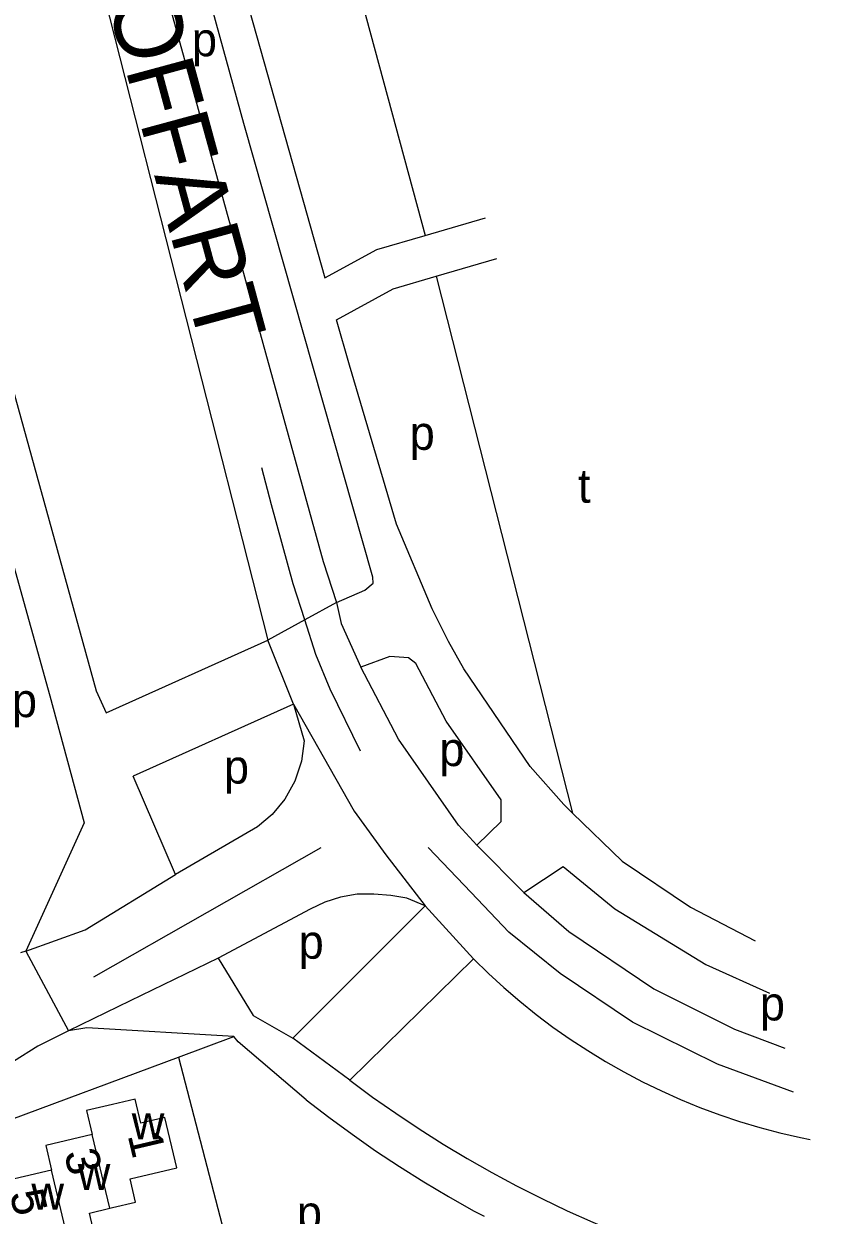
# Model space of a CAD drawing. Extents: x 157646 to 159241, y 379213 to 381217.
# Drawn here: x 159089.5 to 159185.7, y 380734 to 380874.9 of the extents above; entities that cross this region are included whole.
import ezdxf

# ---------------------------------------------------------------- set-up
doc = ezdxf.new("R2010")
doc.units = 0
for name, color, linetype in [('BLT_Basislijn', 7, 'Continuous'), ('BLT_Bebouwing', 7, 'Continuous'), ('BLT_Centroide', 7, 'Continuous'), ('BLT_Huisnummer', 7, 'Continuous'), ('BLT_Huisnummer_ tussenligend', 7, 'Continuous'), ('BLT_Onderverdeling_panden', 7, 'Continuous'), ('BLT_Straatnaam_hoofdweg', 7, 'Continuous'), ('BLT_Vlakafsluiter', 7, 'Continuous')]:
    doc.layers.add(name, color=color, linetype=linetype)

msp = doc.modelspace()

# ---------------------------------------------------------------- linework, layer by layer
at = {"layer": 'BLT_Basislijn'}
for p, q in [((159097.22, 380885.26), (159118.39, 380801.95)), ((159137, 380849.84), (159144.12, 380851.92)), ((159138.27, 380845), (159145.45, 380847.1)), ((159138.27, 380845), (159154.43, 380781.49)), ((159121.41, 380794.39), (159118.39, 380801.95)), ((159121.41, 380794.39), (159102.45, 380785.88)), ((159107.45, 380774.23), (159102.45, 380785.88)), ((159153.37, 380782.52), (159154.43, 380781.49)), ((159096.65, 380780.35), (159089.77, 380765.17)), ((159117.14, 380779.87), (159107.45, 380774.23)), ((159097.8, 380762.14), (159124.67, 380777.46)), ((159148.65, 380772.12), (159143.08, 380777.73)), ((159123.38, 380770.15), (159112.51, 380764.37)), ((159136.99, 380770.53), (159121.34, 380754.91)), ((159136.99, 380770.53), (159142.7, 380764.29)), ((159089.77, 380765.17), (159089.11, 380764.99)), ((159112.51, 380764.37), (159116.63, 380757.59)), ((159142.7, 380764.29), (159128.09, 380749.91)), ((159116.63, 380757.59), (159121.34, 380754.91)), ((159107.8, 380752.64), (159114.36, 380755.08)), ((159128.09, 380749.91), (159121.34, 380754.91)), ((159035.86, 380725.94), (159107.8, 380752.64)), ((159107.8, 380752.64), (159115.84, 380721.89))]:
    msp.add_line(p, q, dxfattribs=at)
for points in [[(159061.42, 381122.18), (159087.3, 381027.91), (159116.68, 380924.86), (159137, 380849.84)], [(159051.94, 381105.75), (159100, 380933.91), (159125.11, 380844.8)], [(159126.48, 380806.41), (159129.85, 380807.86), (159130.83, 380808.7), (159130.78, 380809.42), (159115.53, 380863.06), (159100, 380919.55), (159083.47, 380977.99), (159078.6, 380977.14)], [(159078.6, 380977.14), (159100, 380901.47), (159124.92, 380811.25), (159126.48, 380806.41)], [(159071.61, 380891.71), (159098.09, 380795.96), (159099.25, 380793.36), (159118.39, 380801.95)], [(159125.11, 380844.8), (159131.28, 380848.16), (159137, 380849.84)], [(159126.5, 380839.86), (159133.2, 380843.51), (159138.27, 380845)], [(159153.37, 380782.52), (159149.41, 380787.04), (159141.55, 380798.57), (159139.74, 380801.79), (159137.8, 380805.67), (159133.6, 380815.67), (159128.02, 380834.49), (159126.5, 380839.86)], [(159122.75, 380804.35), (159121.39, 380808.61), (159118.83, 380817.98), (159117.65, 380822.33)], [(159085.81, 380819.61), (159092.6, 380795.38), (159096.65, 380780.35)], [(159126.48, 380806.41), (159127.07, 380803.93), (159129.36, 380798.75)], [(159129.34, 380788.85), (159125.73, 380796.18), (159124.04, 380800.28), (159122.75, 380804.35)], [(159143.08, 380777.73), (159145.97, 380780.53), (159145.99, 380783.08), (159139.48, 380792.38), (159135.89, 380799.21), (159135.03, 380799.89), (159132.8, 380800.02), (159129.36, 380798.75)], [(159143.08, 380777.73), (159140.94, 380780.09), (159133.82, 380790.24), (159129.36, 380798.75)], [(159121.41, 380794.39), (159122.66, 380790.06), (159122.35, 380787.64), (159121.59, 380785.29), (159120.4, 380783.16), (159118.89, 380781.33), (159117.14, 380779.87)], [(159154.43, 380781.49), (159160.28, 380775.81), (159168.37, 380770.37), (159176.02, 380766.39)], [(159180.54, 380748.52), (159171.57, 380751.81), (159161.51, 380756.8), (159152.95, 380762.52), (159146.9, 380767.43), (159142.41, 380772.13), (159137.34, 380777.44)], [(159148.65, 380772.12), (159153.32, 380775.2), (159159.43, 380770.18), (159170.18, 380763.59), (159177.73, 380760.22)], [(159089.77, 380765.17), (159096.79, 380767.72), (159107.45, 380774.23)], [(159148.65, 380772.12), (159153.99, 380767.52), (159164.04, 380760.73), (159173.59, 380755.96), (159179.53, 380753.71)], [(159136.99, 380770.53), (159134.8, 380771.43), (159132.92, 380771.77), (159130.93, 380771.94), (159128.93, 380771.91), (159126.96, 380771.58), (159125.1, 380770.99), (159123.38, 380770.15)], [(159112.51, 380764.37), (159102.08, 380759.31), (159094.81, 380755.74)], [(159142.7, 380764.29), (159144.47, 380762.55), (159146.3, 380760.88), (159148.18, 380759.26), (159150.12, 380757.7), (159152.1, 380756.21), (159154.14, 380754.78), (159156.21, 380753.42), (159158.33, 380752.12), (159160.49, 380750.9), (159162.69, 380749.74), (159164.92, 380748.66), (159167.19, 380747.64), (159169.49, 380746.71), (159171.82, 380745.84), (159174.17, 380745.05), (159176.55, 380744.34), (159178.95, 380743.71), (159181.37, 380743.15), (159182.51, 380742.92)], [(159094.81, 380755.74), (159091.19, 380753.93), (159088.28, 380752.14), (159087.76, 380751.2)], [(159114.36, 380755.08), (159096.98, 380756.11), (159094.81, 380755.74)], [(159122.91, 380747.6), (159114.87, 380754.47), (159114.36, 380755.08)], [(159128.09, 380749.91), (159130.77, 380747.93), (159133.5, 380746.01), (159136.28, 380744.16), (159139.1, 380742.37), (159141.96, 380740.65), (159144.86, 380739), (159147.79, 380737.43), (159150.77, 380735.92), (159153.78, 380734.48), (159156.83, 380733.12), (159159.9, 380731.83), (159163.01, 380730.61), (159166.14, 380729.47), (159169.31, 380728.41), (159172.49, 380727.42), (159175.7, 380726.51), (159178.93, 380725.67), (159182.18, 380724.91), (159185.44, 380724.23), (159185.71, 380724.18)], [(159122.91, 380747.6), (159125.6, 380745.53), (159128.34, 380743.52), (159131.12, 380741.58), (159133.96, 380739.7), (159136.83, 380737.89), (159139.74, 380736.15), (159142.7, 380734.48), (159143.95, 380733.82)]]:
    msp.add_lwpolyline(points, dxfattribs=at)
at = {"layer": 'BLT_Bebouwing'}
msp.add_line((159092.8, 380739.29), (159086.2, 380737.74), dxfattribs=at)
for points in [[(159100.01, 380747.06), (159096.95, 380746.34), (159097.62, 380743.49)], [(159102.09, 380738.24), (159107.61, 380739.55), (159106.2, 380745.52), (159103.34, 380744.84), (159102.67, 380747.69), (159100.01, 380747.06)], [(159097.62, 380743.49), (159092.11, 380742.19), (159092.8, 380739.29)], [(159099.68, 380734.77), (159100, 380734.85), (159102.74, 380735.5), (159102.09, 380738.24)], [(159094.85, 380730.58), (159097.96, 380731.32), (159097.28, 380734.21), (159099.68, 380734.77)]]:
    msp.add_lwpolyline(points, dxfattribs=at)
at = {"layer": 'BLT_Onderverdeling_panden'}
for p, q in [((159099.68, 380734.77), (159097.62, 380743.49)), ((159094.85, 380730.58), (159092.8, 380739.29))]:
    msp.add_line(p, q, dxfattribs=at)
at = {"layer": 'BLT_Vlakafsluiter'}
for p, q in [((159126.48, 380806.41), (159122.75, 380804.35)), ((159122.75, 380804.35), (159118.39, 380801.95)), ((159089.77, 380765.17), (159094.81, 380755.74))]:
    msp.add_line(p, q, dxfattribs=at)
msp.add_lwpolyline([(159121.41, 380794.39), (159128.6, 380781.75), (159132.34, 380776.57), (159136.99, 380770.53)], dxfattribs=at)

# ---------------------------------------------------------------- texts
at = {"layer": 'BLT_Centroide'}
for s, p in [('p', (159109.39, 380871.02)), ('p', (159135.15, 380824.47)), ('t', (159155.06, 380818.22)), ('p', (159088.1, 380792.86)), ('p', (159138.66, 380787.07)), ('p', (159113.18, 380785)), ('p', (159122.02, 380764.29)), ('p', (159176.57, 380756.99)), ('w', (159102.28, 380742.94)), ('w', (159095.89, 380736.95)), ('w', (159090.41, 380734.62)), ('p', (159121.81, 380732.26))]:
    msp.add_text(s, height=4, dxfattribs=at).set_placement(p)
at = {"layer": 'BLT_Huisnummer'}
for s, rotation, p in [('1', 283.2769, (159101.78, 380743.41)), ('5', 283.2786, (159087.83, 380736.53))]:
    msp.add_text(s, height=4, rotation=rotation, dxfattribs=at).set_placement(p)
at = {"layer": 'BLT_Huisnummer_ tussenligend'}
msp.add_text('3', height=4, rotation=283.2769, dxfattribs=at).set_placement((159094.27, 380741.33))
at = {"layer": 'BLT_Straatnaam_hoofdweg'}
msp.add_text('ROFFART', height=8, rotation=285.155, dxfattribs=at).set_placement((159097.31, 380885.05))

doc.saveas('drawing.dxf')
